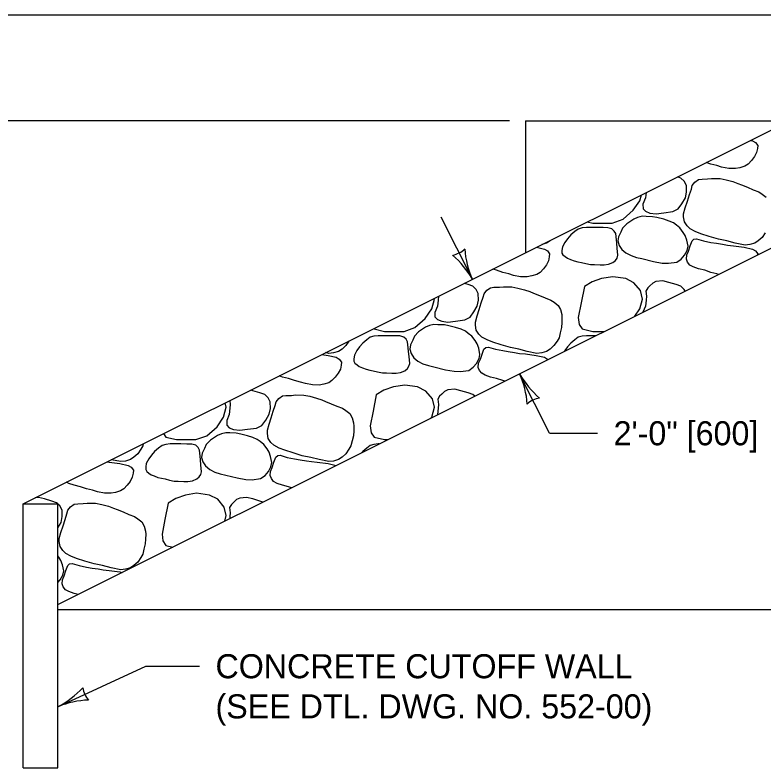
# Model space of a CAD drawing. Extents: x 49991.4 to 50021, y 49987.6 to 50011.4.
# Drawn here: x 50002.203 to 50004.068, y 50004.344 to 50006.22 of the extents above; entities that cross this region are included whole.
import ezdxf

# ---------------------------------------------------------------- set-up
doc = ezdxf.new("R2010")
doc.units = 0
for name, color, linetype in [('Default', 7, 'Continuous'), ('Level 1', 7, 'Continuous'), ('Level 2', 7, 'Continuous'), ('Level 3', 7, 'Continuous')]:
    doc.layers.add(name, color=color, linetype=linetype)

msp = doc.modelspace()

# ---------------------------------------------------------------- linework, layer by layer
at = {"layer": 'Default'}
for points in [[(50004.0348, 50005.908), (50004.0398, 50005.907), (50004.0471, 50005.9025), (50004.0529, 50005.895), (50004.0521, 50005.8876), (50004.05, 50005.8775), (50004.0447, 50005.8674), (50004.0373, 50005.8577), (50004.0291, 50005.8488), (50004.0209, 50005.8435), (50004.0086, 50005.8398), (50003.9971, 50005.8376), (50003.9807, 50005.8379), (50003.963, 50005.8413), (50003.9511, 50005.845), (50003.9359, 50005.8488), (50003.9243, 50005.8528)], [(50003.7749, 50005.7781), (50003.7734, 50005.7644), (50003.7669, 50005.7491), (50003.7673, 50005.7375), (50003.7734, 50005.7312), (50003.7841, 50005.7267), (50003.7997, 50005.7249), (50003.8186, 50005.7275), (50003.8415, 50005.7305), (50003.8547, 50005.7372), (50003.8641, 50005.7502), (50003.8727, 50005.7648), (50003.8756, 50005.7793), (50003.8752, 50005.7958), (50003.8699, 50005.8062), (50003.8617, 50005.814), (50003.8529, 50005.8171)], [(50004.0713, 50005.6775), (50004.0635, 50005.6663), (50004.0541, 50005.6578), (50004.0455, 50005.6518), (50004.0332, 50005.6481), (50004.0213, 50005.6469), (50003.997, 50005.6518), (50003.9761, 50005.6574), (50003.9552, 50005.6615), (50003.9322, 50005.6686), (50003.9113, 50005.6749), (50003.8973, 50005.6805), (50003.8842, 50005.6876), (50003.8768, 50005.6947), (50003.8702, 50005.7048), (50003.8682, 50005.7171), (50003.8682, 50005.7249), (50003.8723, 50005.7402), (50003.8776, 50005.7563), (50003.8826, 50005.7727), (50003.8875, 50005.7865), (50003.8899, 50005.7955), (50003.8965, 50005.804), (50003.9055, 50005.8104), (50003.9142, 50005.8115), (50003.9281, 50005.8119), (50003.938, 50005.813), (50003.9589, 50005.8126), (50003.9741, 50005.8096), (50003.9905, 50005.8052), (50004.0036, 50005.8007), (50004.0126, 50005.797), (50004.0274, 50005.791), (50004.0414, 50005.785), (50004.0557, 50005.7798), (50004.0639, 50005.7742), (50004.0738, 50005.7663)], [(50003.6283, 50005.7048), (50003.6419, 50005.7017), (50003.6903, 50005.7017), (50003.7174, 50005.7114), (50003.7429, 50005.7338), (50003.7593, 50005.7577), (50003.7631, 50005.7722)], [(50003.5378, 50005.6595), (50003.5358, 50005.6578), (50003.5272, 50005.6518), (50003.5149, 50005.6481), (50003.5148, 50005.648)], [(50003.9554, 50005.5739), (50003.9511, 50005.5753), (50003.9359, 50005.579), (50003.9208, 50005.5842), (50003.9056, 50005.588), (50003.8924, 50005.5925), (50003.8838, 50005.5973), (50003.8781, 50005.6044), (50003.8752, 50005.6119), (50003.876, 50005.6223), (50003.8805, 50005.632), (50003.8846, 50005.6451), (50003.8892, 50005.6578), (50003.8941, 50005.6619), (50003.9002, 50005.6626), (50003.9179, 50005.6574), (50003.9359, 50005.6537), (50003.9499, 50005.6514), (50003.9655, 50005.6492), (50003.9778, 50005.6469), (50003.9926, 50005.6454), (50004.0192, 50005.6417), (50004.0398, 50005.6372), (50004.0471, 50005.6328), (50004.0529, 50005.6253), (50004.0526, 50005.6225)], [(50003.5018, 50005.6415), (50003.5215, 50005.6372), (50003.5289, 50005.6328), (50003.5346, 50005.6253), (50003.5338, 50005.6178), (50003.5318, 50005.6078), (50003.5264, 50005.5977), (50003.519, 50005.588), (50003.5108, 50005.579), (50003.5026, 50005.5738), (50003.4903, 50005.5701), (50003.4788, 50005.5678), (50003.4624, 50005.5682), (50003.4448, 50005.5716), (50003.4329, 50005.5753), (50003.4177, 50005.579), (50003.4025, 50005.5842), (50003.3923, 50005.5868)], [(50003.7466, 50005.4696), (50003.7593, 50005.488), (50003.7658, 50005.5126), (50003.7609, 50005.5335), (50003.7445, 50005.5529), (50003.724, 50005.5634), (50003.692, 50005.5678), (50003.6641, 50005.5634), (50003.6403, 50005.5551), (50003.6212, 50005.5436), (50003.6132, 50005.5029), (50003.6058, 50005.4663), (50003.6083, 50005.4492), (50003.6156, 50005.438), (50003.6419, 50005.432), (50003.6715, 50005.432)], [(50003.872, 50005.5323), (50003.8699, 50005.5365), (50003.8617, 50005.5443), (50003.8498, 50005.5484), (50003.8317, 50005.5536), (50003.8165, 50005.5578), (50003.7993, 50005.5559), (50003.7915, 50005.5522), (50003.7845, 50005.5454), (50003.7788, 50005.5402), (50003.7742, 50005.5324), (50003.7759, 50005.5193), (50003.7751, 50005.51), (50003.7734, 50005.4947), (50003.767, 50005.4798)], [(50003.2576, 50005.5194), (50003.2576, 50005.5193), (50003.2568, 50005.51), (50003.2552, 50005.4947), (50003.2486, 50005.4794), (50003.249, 50005.4678), (50003.2552, 50005.4615), (50003.2658, 50005.457), (50003.2814, 50005.4551), (50003.3003, 50005.4577), (50003.3233, 50005.4607), (50003.3364, 50005.4674), (50003.3459, 50005.4805), (50003.3545, 50005.4951), (50003.3574, 50005.5096), (50003.3569, 50005.526), (50003.3516, 50005.5365), (50003.3434, 50005.5443), (50003.3315, 50005.5484), (50003.3214, 50005.5513)], [(50003.0967, 50005.439), (50003.0974, 50005.438), (50003.1236, 50005.432), (50003.1721, 50005.432), (50003.1992, 50005.4417), (50003.2246, 50005.4641), (50003.241, 50005.488), (50003.2476, 50005.5126), (50003.2472, 50005.5142)], [(50003.035, 50005.4081), (50003.0348, 50005.4078), (50003.027, 50005.3966), (50003.0176, 50005.388), (50003.009, 50005.3821), (50002.9967, 50005.3783), (50002.9847, 50005.3772), (50002.9765, 50005.3789)], [(50003.65, 50005.4212), (50003.6376, 50005.4212), (50003.6261, 50005.4212), (50003.6154, 50005.4201), (50003.606, 50005.4171), (50003.5974, 50005.4108), (50003.5875, 50005.4026), (50003.5793, 50005.3933), (50003.5728, 50005.3839), (50003.5718, 50005.3821)], [(50003.4233, 50005.3079), (50003.4177, 50005.3093), (50003.4025, 50005.3145), (50003.3873, 50005.3182), (50003.3742, 50005.3227), (50003.3656, 50005.3276), (50003.3598, 50005.3347), (50003.3569, 50005.3421), (50003.3578, 50005.3526), (50003.3623, 50005.3623), (50003.3664, 50005.3753), (50003.3709, 50005.388), (50003.3758, 50005.3921), (50003.382, 50005.3929), (50003.3996, 50005.3877), (50003.4177, 50005.3839), (50003.4316, 50005.3817), (50003.4472, 50005.3794), (50003.4595, 50005.3772), (50003.4743, 50005.3757), (50003.501, 50005.372), (50003.5215, 50005.3675), (50003.5289, 50005.363), (50003.5302, 50005.3613)], [(50002.9671, 50005.3742), (50002.9827, 50005.372), (50003.0032, 50005.3675), (50003.0106, 50005.363), (50003.0164, 50005.3556), (50003.0156, 50005.3481), (50003.0135, 50005.338), (50003.0082, 50005.328), (50003.0008, 50005.3182), (50002.9926, 50005.3093), (50002.9844, 50005.3041), (50002.9721, 50005.3003), (50002.9606, 50005.2981), (50002.9442, 50005.2985), (50002.9265, 50005.3018), (50002.9146, 50005.3056), (50002.8994, 50005.3093), (50002.8842, 50005.3145), (50002.8691, 50005.3182), (50002.8609, 50005.321)], [(50003.2395, 50005.216), (50003.241, 50005.2182), (50003.2476, 50005.2429), (50003.2427, 50005.2638), (50003.2262, 50005.2832), (50003.2057, 50005.2936), (50003.1737, 50005.2981), (50003.1458, 50005.2936), (50003.122, 50005.2854), (50003.103, 50005.2738), (50003.0949, 50005.2332), (50003.0875, 50005.1966), (50003.09, 50005.1794), (50003.0974, 50005.1682), (50003.1236, 50005.1623), (50003.132, 50005.1623)], [(50002.7381, 50005.2597), (50002.7394, 50005.2496), (50002.7386, 50005.2403), (50002.7369, 50005.225), (50002.7304, 50005.2097), (50002.7308, 50005.1981), (50002.7369, 50005.1917), (50002.7476, 50005.1873), (50002.7632, 50005.1854), (50002.7821, 50005.188), (50002.805, 50005.191), (50002.8182, 50005.1977), (50002.8276, 50005.2108), (50002.8362, 50005.2253), (50002.8391, 50005.2399), (50002.8387, 50005.2563), (50002.8334, 50005.2667), (50002.8251, 50005.2746), (50002.8132, 50005.2787), (50002.7952, 50005.2839), (50002.7896, 50005.2854)], [(50003.348, 50005.2702), (50003.3434, 50005.2746), (50003.3315, 50005.2787), (50003.3134, 50005.2839), (50003.2983, 50005.288), (50003.281, 50005.2862), (50003.2732, 50005.2824), (50003.2663, 50005.2757), (50003.2605, 50005.2705), (50003.256, 50005.2626), (50003.2576, 50005.2496), (50003.2568, 50005.2403), (50003.2552, 50005.225), (50003.2546, 50005.2235)], [(50002.5732, 50005.1772), (50002.5791, 50005.1682), (50002.6054, 50005.1623), (50002.6538, 50005.1623), (50002.6809, 50005.172), (50002.7063, 50005.1944), (50002.7228, 50005.2182), (50002.7293, 50005.2429), (50002.7267, 50005.254)], [(50002.5228, 50005.152), (50002.5215, 50005.1463), (50002.5166, 50005.1381), (50002.5088, 50005.1269), (50002.4993, 50005.1183), (50002.4907, 50005.1123), (50002.4784, 50005.1086), (50002.4665, 50005.1075), (50002.4431, 50005.1122)], [(50003.1105, 50005.1515), (50003.1079, 50005.1515), (50003.0972, 50005.1504), (50003.0877, 50005.1474), (50003.0791, 50005.1411), (50003.0693, 50005.1329), (50003.0662, 50005.1293)], [(50002.8918, 50005.0422), (50002.8842, 50005.0448), (50002.8691, 50005.0485), (50002.8559, 50005.053), (50002.8473, 50005.0578), (50002.8416, 50005.0649), (50002.8387, 50005.0724), (50002.8395, 50005.0829), (50002.844, 50005.0926), (50002.8481, 50005.1056), (50002.8526, 50005.1183), (50002.8576, 50005.1224), (50002.8637, 50005.1232), (50002.8814, 50005.1179), (50002.8994, 50005.1142), (50002.9134, 50005.112), (50002.929, 50005.1097), (50002.9413, 50005.1075), (50002.9561, 50005.106), (50002.9827, 50005.1023), (50003.0031, 50005.0978)], [(50002.432, 50005.1066), (50002.4378, 50005.106), (50002.4645, 50005.1023), (50002.485, 50005.0978), (50002.4924, 50005.0933), (50002.4981, 50005.0858), (50002.4973, 50005.0784), (50002.4953, 50005.0683), (50002.4899, 50005.0582), (50002.4825, 50005.0485), (50002.4743, 50005.0396), (50002.4661, 50005.0343), (50002.4538, 50005.0306), (50002.4423, 50005.0284), (50002.4259, 50005.0287), (50002.4083, 50005.0321), (50002.3964, 50005.0358), (50002.3812, 50005.0396), (50002.366, 50005.0448), (50002.3508, 50005.0485), (50002.3377, 50005.053), (50002.3316, 50005.0564)], [(50002.7256, 50004.959), (50002.7293, 50004.9731), (50002.7244, 50004.994), (50002.708, 50005.0134), (50002.6875, 50005.0239), (50002.6555, 50005.0284), (50002.6276, 50005.0239), (50002.6038, 50005.0157), (50002.5847, 50005.0041), (50002.5767, 50004.9634), (50002.5693, 50004.9269), (50002.5717, 50004.9097), (50002.5791, 50004.8985), (50002.5966, 50004.8945)], [(50002.3096, 50005.0023), (50002.3069, 50005.0049), (50002.295, 50005.009), (50002.2769, 50005.0142), (50002.2618, 50005.0183), (50002.2536, 50005.0174)], [(50002.8205, 50005.0065), (50002.8132, 50005.009), (50002.7952, 50005.0142), (50002.78, 50005.0183), (50002.7628, 50005.0164), (50002.755, 50005.0127), (50002.748, 50005.006), (50002.7423, 50005.0008), (50002.7377, 50004.9929), (50002.7394, 50004.9799), (50002.7386, 50004.9705), (50002.738, 50004.9652)], [(50002.2285, 50005.0049), (50002.2257, 50005.0023)], [(50002.3102, 50004.9425), (50002.318, 50004.9556), (50002.3208, 50004.9702), (50002.3204, 50004.9866), (50002.3151, 50004.997), (50002.3102, 50005.0017)], [(50002.3102, 50004.806), (50002.3159, 50004.8127), (50002.3225, 50004.8247), (50002.3245, 50004.8351), (50002.3217, 50004.8504), (50002.3176, 50004.8613), (50002.3126, 50004.8695), (50002.3102, 50004.8728)], [(50002.3604, 50004.7764), (50002.3508, 50004.7788), (50002.3377, 50004.7833), (50002.3291, 50004.7881), (50002.3233, 50004.7952), (50002.3204, 50004.8027), (50002.3213, 50004.8131), (50002.3258, 50004.8228), (50002.3299, 50004.8359), (50002.3344, 50004.8486), (50002.3393, 50004.8527), (50002.3455, 50004.8534), (50002.3631, 50004.8482), (50002.3812, 50004.8445), (50002.3951, 50004.8422), (50002.4107, 50004.84), (50002.423, 50004.8378), (50002.4378, 50004.8363), (50002.4645, 50004.8325), (50002.4701, 50004.8313)]]:
    msp.add_lwpolyline(points, dxfattribs=at)
for points in [[(50003.7439, 50005.7119), (50003.7267, 50005.7003), (50003.716, 50005.6895), (50003.7119, 50005.6794), (50003.7061, 50005.6678), (50003.7045, 50005.6574), (50003.7078, 50005.6462), (50003.7143, 50005.6361), (50003.7246, 50005.6275), (50003.7373, 50005.6208), (50003.7509, 50005.6163), (50003.7644, 50005.6134), (50003.7931, 50005.6063), (50003.8149, 50005.6022), (50003.8305, 50005.6018), (50003.8514, 50005.6044), (50003.8625, 50005.6122), (50003.8707, 50005.6219), (50003.8773, 50005.6339), (50003.8793, 50005.6443), (50003.8764, 50005.6596), (50003.8723, 50005.6705), (50003.8674, 50005.6787), (50003.8592, 50005.6899), (50003.8502, 50005.6966), (50003.8432, 50005.7022), (50003.8321, 50005.707), (50003.8186, 50005.7115), (50003.8017, 50005.7156), (50003.7907, 50005.7178), (50003.7747, 50005.7182), (50003.7648, 50005.719), (50003.7537, 50005.716)], [(50003.6154, 50005.6899), (50003.606, 50005.6869), (50003.5974, 50005.6805), (50003.5875, 50005.6723), (50003.5793, 50005.663), (50003.5728, 50005.6537), (50003.5666, 50005.6425), (50003.5654, 50005.6335), (50003.5654, 50005.6272), (50003.5678, 50005.6223), (50003.5732, 50005.6182), (50003.5789, 50005.6141), (50003.5867, 50005.6111), (50003.5957, 50005.6074), (50003.6048, 50005.6051), (50003.6138, 50005.6037), (50003.6245, 50005.6007), (50003.6364, 50005.5984), (50003.6462, 50005.5984), (50003.6602, 50005.5977), (50003.6704, 50005.5977), (50003.6815, 50005.5992), (50003.6922, 50005.6037), (50003.6987, 50005.6089), (50003.7024, 50005.6148), (50003.7045, 50005.6216), (50003.7029, 50005.6391), (50003.7016, 50005.6514), (50003.7008, 50005.6604), (50003.6992, 50005.6757), (50003.6955, 50005.682), (50003.6897, 50005.6876), (50003.6799, 50005.6902), (50003.668, 50005.6906), (50003.6528, 50005.691), (50003.6376, 50005.691), (50003.6261, 50005.691)], [(50003.3959, 50005.5418), (50003.4099, 50005.5421), (50003.4197, 50005.5433), (50003.4406, 50005.5429), (50003.4558, 50005.5399), (50003.4722, 50005.5354), (50003.4854, 50005.531), (50003.4944, 50005.5272), (50003.5092, 50005.5212), (50003.5231, 50005.5153), (50003.5375, 50005.5101), (50003.5457, 50005.5045), (50003.5555, 50005.4966), (50003.5613, 50005.4862), (50003.5646, 50005.4739), (50003.5654, 50005.4656), (50003.565, 50005.4537), (50003.5641, 50005.4418), (50003.5609, 50005.4287), (50003.558, 50005.416), (50003.5531, 50005.4078), (50003.5453, 50005.3966), (50003.5358, 50005.388), (50003.5272, 50005.3821), (50003.5149, 50005.3783), (50003.503, 50005.3772), (50003.4788, 50005.3821), (50003.4579, 50005.3876), (50003.4369, 50005.3918), (50003.414, 50005.3988), (50003.393, 50005.4052), (50003.3791, 50005.4108), (50003.3659, 50005.4179), (50003.3586, 50005.425), (50003.352, 50005.435), (50003.3499, 50005.4474), (50003.3499, 50005.4552), (50003.354, 50005.4705), (50003.3594, 50005.4865), (50003.3643, 50005.503), (50003.3692, 50005.5168), (50003.3717, 50005.5257), (50003.3783, 50005.5343), (50003.3873, 50005.5407)], [(50003.2256, 50005.4421), (50003.2084, 50005.4306), (50003.1977, 50005.4198), (50003.1936, 50005.4097), (50003.1879, 50005.3981), (50003.1862, 50005.3877), (50003.1895, 50005.3765), (50003.1961, 50005.3664), (50003.2063, 50005.3578), (50003.2191, 50005.3511), (50003.2326, 50005.3466), (50003.2462, 50005.3436), (50003.2749, 50005.3365), (50003.2966, 50005.3324), (50003.3122, 50005.3321), (50003.3331, 50005.3347), (50003.3442, 50005.3425), (50003.3524, 50005.3522), (50003.359, 50005.3641), (50003.3611, 50005.3746), (50003.3582, 50005.3899), (50003.3541, 50005.4007), (50003.3492, 50005.4089), (50003.3409, 50005.4201), (50003.3319, 50005.4268), (50003.3249, 50005.4324), (50003.3139, 50005.4373), (50003.3003, 50005.4418), (50003.2835, 50005.4459), (50003.2724, 50005.4481), (50003.2564, 50005.4485), (50003.2466, 50005.4492), (50003.2355, 50005.4462)], [(50003.0972, 50005.4201), (50003.0877, 50005.4171), (50003.0791, 50005.4108), (50003.0693, 50005.4026), (50003.0611, 50005.3933), (50003.0545, 50005.3839), (50003.0484, 50005.3727), (50003.0471, 50005.3638), (50003.0471, 50005.3574), (50003.0496, 50005.3526), (50003.0549, 50005.3485), (50003.0607, 50005.3444), (50003.0685, 50005.3414), (50003.0775, 50005.3377), (50003.0865, 50005.3354), (50003.0955, 50005.3339), (50003.1062, 50005.3309), (50003.1181, 50005.3287), (50003.128, 50005.3287), (50003.1419, 50005.328), (50003.1522, 50005.328), (50003.1633, 50005.3294), (50003.1739, 50005.3339), (50003.1805, 50005.3391), (50003.1842, 50005.3451), (50003.1862, 50005.3518), (50003.1846, 50005.3694), (50003.1834, 50005.3817), (50003.1825, 50005.3906), (50003.1809, 50005.4059), (50003.1772, 50005.4123), (50003.1715, 50005.4179), (50003.1616, 50005.4205), (50003.1497, 50005.4209), (50003.1345, 50005.4212), (50003.1193, 50005.4212), (50003.1079, 50005.4212)], [(50002.8776, 50005.272), (50002.8916, 50005.2724), (50002.9014, 50005.2735), (50002.9224, 50005.2732), (50002.9376, 50005.2702), (50002.954, 50005.2657), (50002.9671, 50005.2612), (50002.9761, 50005.2575), (50002.9909, 50005.2515), (50003.0049, 50005.2455), (50003.0192, 50005.2403), (50003.0274, 50005.2347), (50003.0373, 50005.2269), (50003.043, 50005.2164), (50003.0463, 50005.2041), (50003.0471, 50005.1959), (50003.0467, 50005.184), (50003.0459, 50005.172), (50003.0426, 50005.159), (50003.0397, 50005.1463), (50003.0348, 50005.1381), (50003.027, 50005.1269), (50003.0176, 50005.1183), (50003.009, 50005.1123), (50002.9967, 50005.1086), (50002.9847, 50005.1075), (50002.9605, 50005.1123), (50002.9396, 50005.1179), (50002.9187, 50005.122), (50002.8957, 50005.1291), (50002.8748, 50005.1355), (50002.8608, 50005.1411), (50002.8477, 50005.1481), (50002.8403, 50005.1552), (50002.8337, 50005.1653), (50002.8317, 50005.1776), (50002.8317, 50005.1855), (50002.8358, 50005.2008), (50002.8411, 50005.2168), (50002.846, 50005.2332), (50002.851, 50005.247), (50002.8534, 50005.256), (50002.86, 50005.2646), (50002.869, 50005.2709)], [(50002.7074, 50005.1724), (50002.6901, 50005.1608), (50002.6795, 50005.15), (50002.6754, 50005.1399), (50002.6696, 50005.1284), (50002.668, 50005.1179), (50002.6713, 50005.1067), (50002.6778, 50005.0967), (50002.6881, 50005.0881), (50002.7008, 50005.0814), (50002.7144, 50005.0769), (50002.7279, 50005.0739), (50002.7566, 50005.0668), (50002.7784, 50005.0627), (50002.794, 50005.0623), (50002.8149, 50005.0649), (50002.826, 50005.0728), (50002.8342, 50005.0825), (50002.8407, 50005.0944), (50002.8428, 50005.1049), (50002.8399, 50005.1202), (50002.8358, 50005.131), (50002.8309, 50005.1392), (50002.8227, 50005.1504), (50002.8137, 50005.1571), (50002.8067, 50005.1627), (50002.7956, 50005.1676), (50002.7821, 50005.172), (50002.7652, 50005.1761), (50002.7542, 50005.1784), (50002.7382, 50005.1788), (50002.7283, 50005.1795), (50002.7172, 50005.1765)], [(50002.5789, 50005.1504), (50002.5695, 50005.1474), (50002.5609, 50005.1411), (50002.551, 50005.1329), (50002.5428, 50005.1235), (50002.5363, 50005.1142), (50002.5301, 50005.103), (50002.5289, 50005.094), (50002.5289, 50005.0877), (50002.5313, 50005.0829), (50002.5367, 50005.0787), (50002.5424, 50005.0746), (50002.5502, 50005.0717), (50002.5592, 50005.0679), (50002.5683, 50005.0657), (50002.5773, 50005.0642), (50002.588, 50005.0612), (50002.5999, 50005.059), (50002.6097, 50005.059), (50002.6237, 50005.0582), (50002.6339, 50005.0582), (50002.645, 50005.0597), (50002.6557, 50005.0642), (50002.6622, 50005.0694), (50002.6659, 50005.0754), (50002.668, 50005.0821), (50002.6663, 50005.0996), (50002.6651, 50005.112), (50002.6643, 50005.1209), (50002.6626, 50005.1362), (50002.659, 50005.1426), (50002.6532, 50005.1482), (50002.6434, 50005.1508), (50002.6315, 50005.1511), (50002.6163, 50005.1515), (50002.6011, 50005.1515), (50002.5896, 50005.1515)], [(50002.3594, 50005.0023), (50002.3733, 50005.0027), (50002.3832, 50005.0038), (50002.4041, 50005.0034), (50002.4193, 50005.0004), (50002.4357, 50004.996), (50002.4488, 50004.9915), (50002.4579, 50004.9878), (50002.4726, 50004.9818), (50002.4866, 50004.9758), (50002.501, 50004.9706), (50002.5092, 50004.965), (50002.519, 50004.9572), (50002.5248, 50004.9467), (50002.528, 50004.9344), (50002.5289, 50004.9262), (50002.5285, 50004.9142), (50002.5276, 50004.9023), (50002.5244, 50004.8892), (50002.5215, 50004.8766), (50002.5166, 50004.8683), (50002.5088, 50004.8571), (50002.4993, 50004.8486), (50002.4907, 50004.8426), (50002.4784, 50004.8389), (50002.4665, 50004.8377), (50002.4423, 50004.8426), (50002.4214, 50004.8482), (50002.4004, 50004.8523), (50002.3774, 50004.8594), (50002.3565, 50004.8657), (50002.3426, 50004.8713), (50002.3294, 50004.8784), (50002.322, 50004.8855), (50002.3155, 50004.8956), (50002.3134, 50004.9079), (50002.3134, 50004.9157), (50002.3175, 50004.931), (50002.3229, 50004.9471), (50002.3278, 50004.9635), (50002.3327, 50004.9773), (50002.3352, 50004.9863), (50002.3417, 50004.9949), (50002.3508, 50005.0012)]]:
    msp.add_lwpolyline(points, close=True, dxfattribs=at)
at = {"layer": 'Level 1'}
for p, q in [((50002.2234, 50005.0023), (50004.6593, 50006.2203)), ((50002.3102, 50004.7514), (50005.2481, 50006.2203)), ((50003.4749, 50005.957), (50004.1327, 50005.957)), ((50003.4749, 50005.957), (50003.4749, 50005.6281)), ((50002.2234, 50004.3439), (50002.2234, 50005.0023)), ((50002.2234, 50005.0023), (50002.3102, 50005.0023)), ((50002.3102, 50004.3439), (50002.3102, 50005.0023)), ((50002.3102, 50004.7389), (50007.2456, 50004.7389)), ((50002.2234, 50004.3439), (50002.3102, 50004.3439))]:
    msp.add_line(p, q, dxfattribs=at)
at = {"layer": 'Level 3'}
for p, q in [((50004.6193, 50006.2203), (50001.628, 50006.2203)), ((50003.4349, 50005.957), (50001.628, 50005.957)), ((50003.3422, 50005.5617), (50003.2646, 50005.7168)), ((50003.5342, 50005.178), (50003.4599, 50005.3262)), ((50003.5342, 50005.178), (50003.6539, 50005.178)), ((50002.3102, 50004.4965), (50002.5288, 50004.5974)), ((50002.5288, 50004.5974), (50002.6625, 50004.5974))]:
    msp.add_line(p, q, dxfattribs=at)
for centre, radius, start, end in [((50003.2848, 50005.6764), 0.0548, 278.7467, 314.4691), ((50003.5449, 50005.653), 0.2223, 184.0639, 204.2474), ((50003.1393, 50005.4472), 0.233, 29.4352, 48.685), ((50003.2572, 50005.2348), 0.2223, 4.0853, 24.2689), ((50003.6628, 50005.4408), 0.233, 209.4566, 228.7065), ((50003.5174, 50005.2116), 0.0548, 98.7682, 134.4905), ((50002.2022, 50004.703), 0.233, 297.6041, 316.854), ((50002.4266, 50004.5502), 0.0548, 186.9156, 222.638), ((50002.395, 50004.291), 0.2223, 92.2328, 112.4163)]:
    msp.add_arc(centre, radius, start, end, dxfattribs=at)

# ---------------------------------------------------------------- texts
at = {"layer": 'Level 2'}
for s, p in [('2\'-0" [600]', (50003.6939, 50005.148)), ('CONCRETE CUTOFF WALL', (50002.7025, 50004.5674)), ('(SEE DTL. DWG. NO. 552-00)', (50002.7025, 50004.4674))]:
    msp.add_text(s, height=0.06, dxfattribs=at).set_placement(p)

doc.saveas('drawing.dxf')
